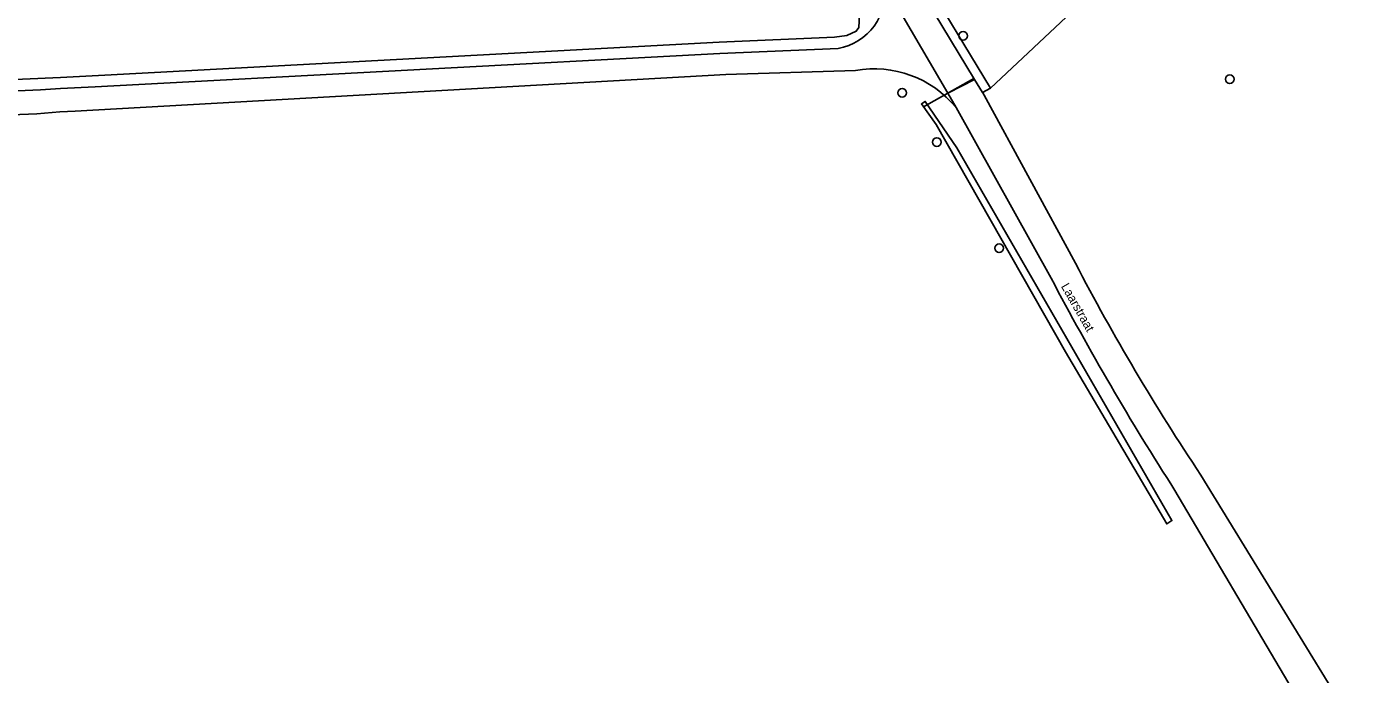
# Model space of a CAD drawing. Extents: x 160203 to 161526, y 379529 to 381797.
# Drawn here: x 160317.7 to 160466.9, y 379773 to 379846.1 of the extents above; entities that cross this region are included whole.
import ezdxf

# ---------------------------------------------------------------- set-up
doc = ezdxf.new("R2010")
doc.units = 0
for name, color, linetype in [('IMGEO_Boom', 7, 'Continuous'), ('IMGEO_Grasland_overig', 7, 'Continuous'), ('IMGEO_Hek', 7, 'Continuous'), ('IMGEO_Naaldbos', 7, 'Continuous'), ('IMGEO_Openbare_ruimte_label', 7, 'Continuous'), ('IMGEO_Rijbaan_lokaal_gesloten', 7, 'Continuous'), ('IMGEO_Rijbaan_lokaal_halfverhard', 7, 'Continuous'), ('IMGEO_Waterloop', 7, 'Continuous')]:
    doc.layers.add(name, color=color, linetype=linetype)

msp = doc.modelspace()

# ---------------------------------------------------------------- linework, layer by layer
at = {"layer": 'IMGEO_Boom'}
for centre in [(160423.32, 379845.05), (160453.38, 379840.16), (160416.46, 379838.63), (160420.36, 379833.08), (160427.38, 379821.1)]:
    msp.add_circle(centre, 0.489, dxfattribs=at)
at = {"layer": 'IMGEO_Grasland_overig'}
for points in [[(160576.07, 379979.7), (160426.4, 379839.14)], [(160368.22, 379945.15), (160370.16, 379942.26), (160371, 379932.38), (160383.71, 379910.71), (160394.58, 379892.15), (160410.1, 379866.11), (160426.4, 379839.14)], [(160426.4, 379839.14), (160425.52, 379838.65)]]:
    msp.add_lwpolyline(points, dxfattribs=at)
at = {"layer": 'IMGEO_Hek'}
for points in [[(160424.55, 379840.26), (160418.86, 379837.04)], [(160425.52, 379838.65), (160426.4, 379839.14)]]:
    msp.add_lwpolyline(points, dxfattribs=at)
at = {"layer": 'IMGEO_Naaldbos'}
msp.add_lwpolyline([(160289.38, 379848.46), (160285.52, 379842.88), (160285.39, 379842.42), (160285.36, 379841.67), (160285.4, 379841.12), (160285.57, 379840.56), (160286.32, 379839.16), (160293.26, 379839.13), (160321.57, 379840.37), (160326.56, 379840.64), (160395.84, 379844.33), (160408.84, 379844.89), (160410.21, 379845.08), (160411.28, 379845.6), (160411.57, 379846), (160411.66, 379847.42)], dxfattribs=at)
at = {"layer": 'IMGEO_Rijbaan_lokaal_gesloten'}
for points in [[(160424.62, 379840.15), (160409.24, 379865.59), (160393.72, 379891.65), (160383.03, 379909.88), (160362.12, 379945.53), (160355.43, 379957.61)], [(160414.5, 379850.79), (160421.59, 379838.6)], [(160421.59, 379838.6), (160424.62, 379840.15)], [(160425.52, 379838.65), (160424.62, 379840.15)], [(160421.59, 379838.6), (160422.53, 379836.98)], [(160425.52, 379838.65), (160425.54, 379838.62), (160425.7, 379838.36), (160435.98, 379819.4)], [(160433.25, 379817.74), (160422.53, 379836.98)], [(160450.12, 379795.52), (160467.63, 379766.93), (160470.83, 379761.7), (160478.64, 379750), (160480.94, 379746.53), (160484.53, 379741.3), (160487.06, 379737.02), (160486.15, 379736.46)], [(160484.53, 379735.46), (160482.04, 379736.75), (160477.11, 379744.07), (160472.68, 379750.63), (160447.21, 379793.79)]]:
    msp.add_lwpolyline(points, dxfattribs=at)
for centre, radius, start, end in [((160663.33, 379937.86), 256.35, 207.5206, 213.7272), ((160714.26, 379965.55), 317.52, 207.7449, 212.7492)]:
    msp.add_arc(centre, radius, start, end, dxfattribs=at)
at = {"layer": 'IMGEO_Rijbaan_lokaal_halfverhard'}
for points in [[(160286.85, 379837.88), (160287.76, 379837.92), (160293.31, 379837.85), (160319.31, 379838.95), (160321.59, 379839.1), (160325.47, 379839.3), (160395.9, 379843.05), (160409.23, 379843.63)], [(160411.2, 379841.14), (160396.58, 379840.7), (160323.24, 379836.57), (160321.51, 379836.48), (160318.92, 379836.26), (160293.16, 379835.24), (160291.01, 379835.51), (160288.84, 379835.58), (160286.68, 379835.45), (160284.53, 379835.14), (160282.42, 379834.63), (160280.37, 379833.93), (160278.38, 379833.06), (160276.48, 379832.01), (160274.68, 379830.79), (160274.08, 379830.33), (160270.95, 379827.61), (160267.17, 379824.85), (160263.16, 379822.44)]]:
    msp.add_lwpolyline(points, dxfattribs=at)
for centre, radius, start, end in [((160408.08, 379850), 6.47, 280.2664, 6.9736), ((160413.33, 379829.44), 11.89, 39.3313, 100.3376)]:
    msp.add_arc(centre, radius, start, end, dxfattribs=at)
at = {"layer": 'IMGEO_Waterloop'}
msp.add_lwpolyline([(160422.62, 379832.43), (160419.06, 379837.66), (160418.62, 379837.38), (160420.29, 379835.05), (160434.87, 379809.43), (160446.29, 379790.01), (160446.87, 379790.38), (160422.62, 379832.43)], dxfattribs=at)

# ---------------------------------------------------------------- texts
at = {"layer": 'IMGEO_Openbare_ruimte_label'}
msp.add_text('Laarstraat', height=1, rotation=299.7165, dxfattribs=at).set_placement((160434.33, 379816.81))

doc.saveas('drawing.dxf')
